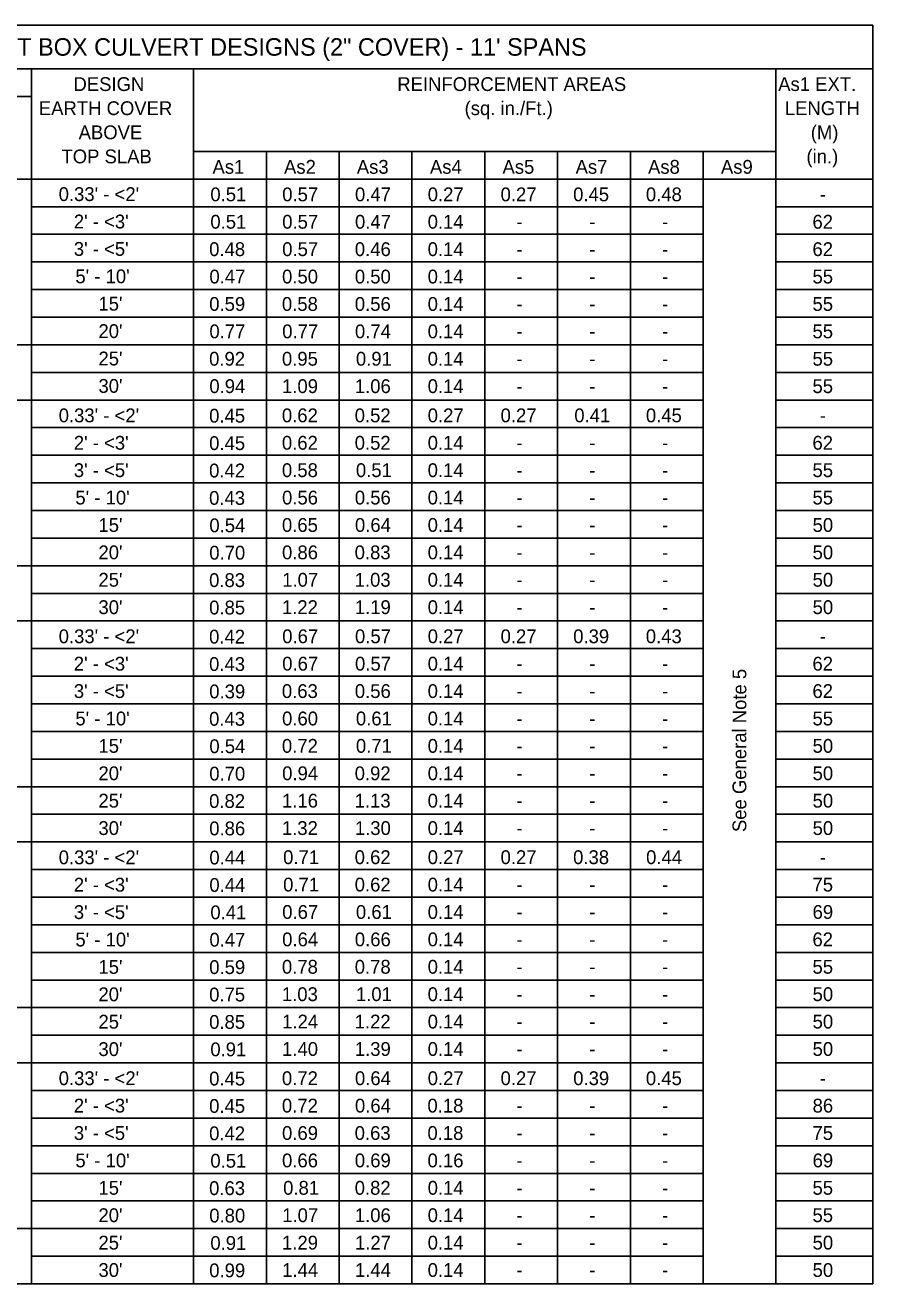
# Model space of a CAD drawing. Extents: x 10351.18 to 10353.4, y 76399.49 to 76400.59.
# Drawn here: x 10351.4 to 10351.787, y 76399.925 to 76400.5 of the extents above; entities that cross this region are included whole.
import ezdxf

# ---------------------------------------------------------------- set-up
doc = ezdxf.new("R2010")
doc.units = 0
doc.layers.add('AdhocPoint_dp', color=7, linetype='Continuous')
doc.layers.add('PlotBorder_dp', color=7, linetype='Continuous')

msp = doc.modelspace()

# ---------------------------------------------------------------- linework, layer by layer
at = {"layer": 'PlotBorder_dp'}
for p, q in [((10351.19191, 76400.49971), (10351.78665, 76400.49971)), ((10351.78665, 76400.49971), (10351.78665, 76399.92549)), ((10351.19191, 76400.47984), (10351.78665, 76400.47984)), ((10351.40299, 76400.47984), (10351.40299, 76399.92549)), ((10351.47687, 76400.47984), (10351.47687, 76399.92549)), ((10351.74246, 76400.47984), (10351.74246, 76399.92549)), ((10351.26055, 76400.46724), (10351.40299, 76400.46724)), ((10351.47687, 76400.44209), (10351.74246, 76400.44209)), ((10351.51007, 76400.44209), (10351.51007, 76399.92549)), ((10351.54327, 76400.44209), (10351.54327, 76399.92549)), ((10351.57647, 76400.44209), (10351.57647, 76399.92549)), ((10351.60967, 76400.44209), (10351.60967, 76399.92549)), ((10351.64287, 76400.44209), (10351.64287, 76399.92549)), ((10351.64287, 76400.44209), (10351.64287, 76399.92549)), ((10351.67606, 76400.44209), (10351.67606, 76399.92549)), ((10351.70926, 76400.44209), (10351.70926, 76399.92549)), ((10351.19191, 76400.42949), (10351.78665, 76400.42949)), ((10351.40299, 76400.41689), (10351.70926, 76400.41689)), ((10351.74246, 76400.41689), (10351.78665, 76400.41689)), ((10351.40299, 76400.40429), (10351.70926, 76400.40429)), ((10351.74246, 76400.40429), (10351.78665, 76400.40429)), ((10351.40299, 76400.39169), (10351.70926, 76400.39169)), ((10351.74246, 76400.39169), (10351.78665, 76400.39169)), ((10351.40299, 76400.37909), (10351.70926, 76400.37909)), ((10351.74246, 76400.37909), (10351.78665, 76400.37909)), ((10351.40299, 76400.36649), (10351.70926, 76400.36649)), ((10351.74246, 76400.36649), (10351.78665, 76400.36649)), ((10351.40299, 76400.35389), (10351.26055, 76400.35389)), ((10351.40299, 76400.35389), (10351.70926, 76400.35389)), ((10351.74246, 76400.35389), (10351.78665, 76400.35389)), ((10351.40299, 76400.34129), (10351.70926, 76400.34129)), ((10351.74246, 76400.34129), (10351.78665, 76400.34129)), ((10351.19191, 76400.32869), (10351.70926, 76400.32869)), ((10351.74246, 76400.32869), (10351.78665, 76400.32869)), ((10351.40299, 76400.31609), (10351.70926, 76400.31609)), ((10351.74246, 76400.31609), (10351.78665, 76400.31609)), ((10351.40299, 76400.30349), (10351.70926, 76400.30349)), ((10351.74246, 76400.30349), (10351.78665, 76400.30349)), ((10351.40299, 76400.29089), (10351.70926, 76400.29089)), ((10351.74246, 76400.29089), (10351.78665, 76400.29089)), ((10351.40299, 76400.27829), (10351.70926, 76400.27829)), ((10351.74246, 76400.27829), (10351.78665, 76400.27829)), ((10351.40299, 76400.26569), (10351.70926, 76400.26569)), ((10351.74246, 76400.26569), (10351.78665, 76400.26569)), ((10351.40299, 76400.25309), (10351.26055, 76400.25309)), ((10351.40299, 76400.25309), (10351.70926, 76400.25309)), ((10351.74246, 76400.25309), (10351.78665, 76400.25309)), ((10351.40299, 76400.24049), (10351.70926, 76400.24049)), ((10351.74246, 76400.24049), (10351.78665, 76400.24049)), ((10351.19191, 76400.22789), (10351.70926, 76400.22789)), ((10351.40362, 76400.22789), (10351.4758, 76400.22789)), ((10351.74246, 76400.22789), (10351.78665, 76400.22789)), ((10351.40299, 76400.21529), (10351.70926, 76400.21529)), ((10351.74246, 76400.21529), (10351.78665, 76400.21529)), ((10351.40299, 76400.20269), (10351.70926, 76400.20269)), ((10351.74246, 76400.20269), (10351.78665, 76400.20269)), ((10351.40299, 76400.19009), (10351.70926, 76400.19009)), ((10351.74246, 76400.19009), (10351.78665, 76400.19009)), ((10351.40299, 76400.17749), (10351.70926, 76400.17749)), ((10351.74246, 76400.17749), (10351.78665, 76400.17749)), ((10351.40299, 76400.16489), (10351.70926, 76400.16489)), ((10351.74246, 76400.16489), (10351.78665, 76400.16489)), ((10351.40299, 76400.15229), (10351.26055, 76400.15229)), ((10351.40299, 76400.15229), (10351.70926, 76400.15229)), ((10351.74246, 76400.15229), (10351.78665, 76400.15229)), ((10351.40299, 76400.13969), (10351.70926, 76400.13969)), ((10351.74246, 76400.13969), (10351.78665, 76400.13969)), ((10351.19191, 76400.12709), (10351.70926, 76400.12709)), ((10351.40362, 76400.12709), (10351.4758, 76400.12709)), ((10351.40362, 76400.12709), (10351.4758, 76400.12709)), ((10351.74246, 76400.12709), (10351.78665, 76400.12709)), ((10351.40299, 76400.11449), (10351.70926, 76400.11449)), ((10351.74246, 76400.11449), (10351.78665, 76400.11449)), ((10351.40299, 76400.10189), (10351.70926, 76400.10189)), ((10351.74246, 76400.10189), (10351.78665, 76400.10189)), ((10351.40299, 76400.08929), (10351.70926, 76400.08929)), ((10351.74246, 76400.08929), (10351.78665, 76400.08929)), ((10351.40299, 76400.07669), (10351.70926, 76400.07669)), ((10351.74246, 76400.07669), (10351.78665, 76400.07669)), ((10351.40299, 76400.06409), (10351.70926, 76400.06409)), ((10351.74246, 76400.06409), (10351.78665, 76400.06409)), ((10351.40299, 76400.05149), (10351.26055, 76400.05149)), ((10351.40299, 76400.05149), (10351.70926, 76400.05149)), ((10351.74246, 76400.05149), (10351.78665, 76400.05149)), ((10351.40299, 76400.03889), (10351.70926, 76400.03889)), ((10351.74246, 76400.03889), (10351.78665, 76400.03889)), ((10351.19191, 76400.02629), (10351.70926, 76400.02629)), ((10351.40362, 76400.02629), (10351.4758, 76400.02629)), ((10351.40362, 76400.02629), (10351.4758, 76400.02629)), ((10351.40362, 76400.02629), (10351.4758, 76400.02629)), ((10351.74246, 76400.02629), (10351.78665, 76400.02629)), ((10351.40299, 76400.01369), (10351.70926, 76400.01369)), ((10351.74246, 76400.01369), (10351.78665, 76400.01369)), ((10351.40299, 76400.00109), (10351.70926, 76400.00109)), ((10351.74246, 76400.00109), (10351.78665, 76400.00109)), ((10351.40299, 76399.98849), (10351.70926, 76399.98849)), ((10351.74246, 76399.98849), (10351.78665, 76399.98849)), ((10351.40299, 76399.97589), (10351.70926, 76399.97589)), ((10351.74246, 76399.97589), (10351.78665, 76399.97589)), ((10351.40299, 76399.96329), (10351.70926, 76399.96329)), ((10351.74246, 76399.96329), (10351.78665, 76399.96329)), ((10351.40299, 76399.95069), (10351.26055, 76399.95069)), ((10351.40299, 76399.95069), (10351.70926, 76399.95069)), ((10351.74246, 76399.95069), (10351.78665, 76399.95069)), ((10351.40299, 76399.93809), (10351.70926, 76399.93809)), ((10351.74246, 76399.93809), (10351.78665, 76399.93809)), ((10351.19191, 76399.92549), (10351.78665, 76399.92549))]:
    msp.add_line(p, q, dxfattribs=at)

# ---------------------------------------------------------------- texts
at = {"layer": 'AdhocPoint_dp'}
for s, height, p in [('TABLE 7 - STANDARD PRECAST BOX CULVERT DESIGNS (2" COVER) - 11\' SPANS', 0.008, (10351.23831, 76400.48578)), ('As1', 0.0063, (10351.48549, 76400.43192)), ('As2', 0.0063, (10351.51812, 76400.43192)), ('As3', 0.0063, (10351.55132, 76400.43192)), ('As4', 0.0063, (10351.58465, 76400.43192)), ('As5', 0.0063, (10351.61775, 76400.43192)), ('As7', 0.0063, (10351.65109, 76400.43192)), ('As8', 0.0063, (10351.68413, 76400.43192)), ('As9', 0.0063, (10351.71738, 76400.43192))]:
    msp.add_text(s, height=height, dxfattribs=at).set_placement(p)
msp.add_text('See General Note 5', height=0.0063, rotation=90, dxfattribs=at).set_placement((10351.72896, 76400.13159))
at = {"layer": 'PlotBorder_dp'}
for s, p in [('DESIGN', (10351.42209, 76400.46968)), ('REINFORCEMENT AREAS', (10351.56977, 76400.46968)), ('(sq. in./Ft.)', (10351.60047, 76400.45868)), ('EARTH COVER', (10351.4063, 76400.45868)), ('ABOVE', (10351.42444, 76400.44768)), ('TOP SLAB', (10351.41661, 76400.43668)), ("0.33' - <2'", (10351.41535, 76400.41948)), ('0.51', (10351.48452, 76400.41937)), ('0.57', (10351.51729, 76400.41937)), ('0.47', (10351.55049, 76400.41937)), ('0.27', (10351.58365, 76400.41937)), ('0.27', (10351.61688, 76400.41937)), ('0.45', (10351.64997, 76400.41937)), ('0.48', (10351.68315, 76400.41937)), ("2' - <3'", (10351.42225, 76400.40698)), ('0.51', (10351.48452, 76400.40687)), ('0.57', (10351.51729, 76400.40687)), ('0.47', (10351.55049, 76400.40687)), ('0.14', (10351.58363, 76400.40687)), ('-', (10351.62414, 76400.40687)), ('-', (10351.65735, 76400.40687)), ('-', (10351.69053, 76400.40687)), ("3' - <5'", (10351.42225, 76400.39448)), ('0.48', (10351.48397, 76400.39437)), ('0.57', (10351.51729, 76400.39437)), ('0.46', (10351.55041, 76400.39437)), ('0.14', (10351.58363, 76400.39437)), ('-', (10351.62414, 76400.39437)), ('-', (10351.65735, 76400.39437)), ('-', (10351.69053, 76400.39437)), ("5' - 10'", (10351.42296, 76400.38198)), ('0.47', (10351.48409, 76400.38187)), ('0.50', (10351.51722, 76400.38187)), ('0.50', (10351.55043, 76400.38187)), ('0.14', (10351.58363, 76400.38187)), ('-', (10351.62414, 76400.38187)), ('-', (10351.65735, 76400.38187)), ('-', (10351.69053, 76400.38187)), ("15'", (10351.43348, 76400.36948)), ('0.59', (10351.48401, 76400.36937)), ('0.58', (10351.51716, 76400.36937)), ('0.56', (10351.55041, 76400.36937)), ('0.14', (10351.58363, 76400.36937)), ('-', (10351.62414, 76400.36937)), ('-', (10351.65735, 76400.36937)), ('-', (10351.69053, 76400.36937)), ("20'", (10351.43348, 76400.35698)), ('0.77', (10351.48409, 76400.35687)), ('0.77', (10351.51729, 76400.35687)), ('0.74', (10351.55047, 76400.35687)), ('0.14', (10351.58363, 76400.35687)), ('-', (10351.62414, 76400.35687)), ('-', (10351.65735, 76400.35687)), ('-', (10351.69053, 76400.35687)), ("25'", (10351.43348, 76400.34448)), ('0.92', (10351.48395, 76400.34437)), ('0.95', (10351.51717, 76400.34437)), ('0.91', (10351.55091, 76400.34437)), ('0.14', (10351.58363, 76400.34437)), ('-', (10351.62414, 76400.34437)), ('-', (10351.65735, 76400.34437)), ('-', (10351.69053, 76400.34437)), ("30'", (10351.43348, 76400.33198)), ('0.94', (10351.48407, 76400.33187)), ('1.09', (10351.51721, 76400.33187)), ('1.06', (10351.55041, 76400.33187)), ('0.14', (10351.58363, 76400.33187)), ('-', (10351.62414, 76400.33187)), ('-', (10351.65735, 76400.33187)), ('-', (10351.69053, 76400.33187)), ("0.33' - <2'", (10351.41535, 76400.31854)), ('0.45', (10351.48397, 76400.31838)), ('0.62', (10351.51715, 76400.31854)), ('0.52', (10351.55035, 76400.31854)), ('0.27', (10351.58365, 76400.31854)), ('0.27', (10351.61688, 76400.31854)), ('0.41', (10351.65051, 76400.31854)), ('0.45', (10351.68315, 76400.31854)), ('-', (10351.76245, 76400.31854)), ("2' - <3'", (10351.42225, 76400.30604)), ('0.45', (10351.48397, 76400.30588)), ('0.62', (10351.51715, 76400.30604)), ('0.52', (10351.55035, 76400.30604)), ('0.14', (10351.58363, 76400.30604)), ('62', (10351.75912, 76400.30604)), ('-', (10351.62414, 76400.30604)), ('-', (10351.65735, 76400.30604)), ('-', (10351.69053, 76400.30604)), ("3' - <5'", (10351.42225, 76400.29354)), ('0.42', (10351.48395, 76400.29338)), ('0.58', (10351.51716, 76400.29354)), ('0.51', (10351.55091, 76400.29354)), ('0.14', (10351.58363, 76400.29354)), ('55', (10351.75914, 76400.29354)), ('-', (10351.62414, 76400.29354)), ('-', (10351.65735, 76400.29354)), ('-', (10351.69053, 76400.29354)), ("5' - 10'", (10351.42296, 76400.28104)), ('0.43', (10351.48394, 76400.28088)), ('0.56', (10351.51721, 76400.28104)), ('0.56', (10351.55041, 76400.28104)), ('0.14', (10351.58363, 76400.28104)), ('55', (10351.75914, 76400.28104)), ('-', (10351.62414, 76400.28104)), ('-', (10351.65735, 76400.28104)), ('-', (10351.69053, 76400.28104)), ("15'", (10351.43348, 76400.26854)), ('0.54', (10351.48407, 76400.26838)), ('0.65', (10351.51717, 76400.26854)), ('0.64', (10351.55047, 76400.26854)), ('0.14', (10351.58363, 76400.26854)), ('-', (10351.62414, 76400.26854)), ('-', (10351.65735, 76400.26854)), ('-', (10351.69053, 76400.26854)), ('50', (10351.75919, 76400.26854)), ("20'", (10351.43348, 76400.25604)), ('0.70', (10351.48403, 76400.25588)), ('0.86', (10351.51721, 76400.25604)), ('0.83', (10351.55034, 76400.25604)), ('0.14', (10351.58363, 76400.25604)), ('-', (10351.62414, 76400.25604)), ('-', (10351.65735, 76400.25604)), ('-', (10351.69053, 76400.25604)), ('50', (10351.75919, 76400.25604)), ("25'", (10351.43348, 76400.24354)), ('0.83', (10351.48394, 76400.24338)), ('1.07', (10351.51729, 76400.24354)), ('1.03', (10351.55034, 76400.24354)), ('0.14', (10351.58363, 76400.24354)), ('50', (10351.75919, 76400.24354)), ('-', (10351.62414, 76400.24354)), ('-', (10351.65735, 76400.24354)), ('-', (10351.69053, 76400.24354)), ("30'", (10351.43348, 76400.23104)), ('0.85', (10351.48397, 76400.23088)), ('1.22', (10351.51715, 76400.23104)), ('1.19', (10351.55041, 76400.23104)), ('0.14', (10351.58363, 76400.23104)), ('50', (10351.75919, 76400.23104)), ('-', (10351.62414, 76400.23104)), ('-', (10351.65735, 76400.23104)), ('-', (10351.69053, 76400.23104)), ("0.33' - <2'", (10351.41535, 76400.21776)), ('0.67', (10351.51729, 76400.21776)), ('0.57', (10351.55049, 76400.21776)), ('0.27', (10351.58365, 76400.21776)), ('0.27', (10351.61688, 76400.21776)), ('0.39', (10351.65001, 76400.21776)), ('0.43', (10351.68312, 76400.21776)), ('0.42', (10351.48395, 76400.2176)), ('-', (10351.76245, 76400.21776)), ("2' - <3'", (10351.42225, 76400.20526)), ('0.43', (10351.48394, 76400.2051)), ('0.67', (10351.51729, 76400.20526)), ('0.57', (10351.55049, 76400.20526)), ('0.14', (10351.58363, 76400.20526)), ('-', (10351.62414, 76400.20526)), ('-', (10351.65735, 76400.20526)), ('-', (10351.69053, 76400.20526)), ('62', (10351.75912, 76400.20526)), ("3' - <5'", (10351.42225, 76400.19276)), ('0.39', (10351.48401, 76400.1926)), ('0.63', (10351.51714, 76400.19276)), ('0.56', (10351.55041, 76400.19276)), ('0.14', (10351.58363, 76400.19276)), ('-', (10351.62414, 76400.19276)), ('-', (10351.65735, 76400.19276)), ('-', (10351.69053, 76400.19276)), ('62', (10351.75912, 76400.19276)), ("5' - 10'", (10351.42296, 76400.18026)), ('0.43', (10351.48394, 76400.1801)), ('0.60', (10351.51722, 76400.18026)), ('0.61', (10351.55091, 76400.18026)), ('0.14', (10351.58363, 76400.18026)), ('55', (10351.75914, 76400.18026)), ('-', (10351.62414, 76400.18026)), ('-', (10351.65735, 76400.18026)), ('-', (10351.69053, 76400.18026)), ("15'", (10351.43348, 76400.16776)), ('0.54', (10351.48407, 76400.1676)), ('0.72', (10351.51715, 76400.16776)), ('0.71', (10351.55091, 76400.16776)), ('0.14', (10351.58363, 76400.16776)), ('50', (10351.75919, 76400.16776)), ('-', (10351.62414, 76400.16776)), ('-', (10351.65735, 76400.16776)), ('-', (10351.69053, 76400.16776)), ("20'", (10351.43348, 76400.15526)), ('0.70', (10351.48403, 76400.1551)), ('0.94', (10351.51727, 76400.15526)), ('0.92', (10351.55035, 76400.15526)), ('0.14', (10351.58363, 76400.15526)), ('50', (10351.75919, 76400.15526)), ('-', (10351.62414, 76400.15526)), ('-', (10351.65735, 76400.15526)), ('-', (10351.69053, 76400.15526)), ("25'", (10351.43348, 76400.14276)), ('0.82', (10351.48395, 76400.1426)), ('1.16', (10351.51721, 76400.14276)), ('1.13', (10351.55034, 76400.14276)), ('0.14', (10351.58363, 76400.14276)), ('-', (10351.62414, 76400.14276)), ('-', (10351.65735, 76400.14276)), ('-', (10351.69053, 76400.14276)), ('50', (10351.75919, 76400.14276)), ("30'", (10351.43348, 76400.13026)), ('0.86', (10351.48401, 76400.1301)), ('1.32', (10351.51715, 76400.13026)), ('1.30', (10351.55043, 76400.13026)), ('0.14', (10351.58363, 76400.13026)), ('-', (10351.62414, 76400.13026)), ('-', (10351.65735, 76400.13026)), ('-', (10351.69053, 76400.13026)), ('50', (10351.75919, 76400.13026)), ("0.33' - <2'", (10351.41535, 76400.11692)), ('0.44', (10351.48407, 76400.11682)), ('0.71', (10351.51771, 76400.11698)), ('0.62', (10351.55035, 76400.11698)), ('0.27', (10351.58365, 76400.11698)), ('0.27', (10351.61688, 76400.11698)), ('0.38', (10351.64996, 76400.11698)), ('0.44', (10351.68325, 76400.11698)), ('-', (10351.76245, 76400.11698)), ("2' - <3'", (10351.42225, 76400.10442)), ('0.44', (10351.48407, 76400.10432)), ('0.71', (10351.51771, 76400.10448)), ('0.62', (10351.55035, 76400.10448)), ('0.14', (10351.58363, 76400.10448)), ('75', (10351.75914, 76400.10448)), ('-', (10351.62414, 76400.10448)), ('-', (10351.65735, 76400.10448)), ('-', (10351.69053, 76400.10448)), ("3' - <5'", (10351.42225, 76400.09192)), ('0.41', (10351.48452, 76400.09182)), ('0.67', (10351.51729, 76400.09198)), ('0.61', (10351.55091, 76400.09198)), ('0.14', (10351.58363, 76400.09198)), ('69', (10351.75918, 76400.09198)), ('-', (10351.62414, 76400.09198)), ('-', (10351.65735, 76400.09198)), ('-', (10351.69053, 76400.09198)), ("5' - 10'", (10351.42296, 76400.07942)), ('0.47', (10351.48409, 76400.07932)), ('0.64', (10351.51727, 76400.07948)), ('0.66', (10351.55041, 76400.07948)), ('0.14', (10351.58363, 76400.07948)), ('-', (10351.62414, 76400.07948)), ('-', (10351.65735, 76400.07948)), ('-', (10351.69053, 76400.07948)), ('62', (10351.75912, 76400.07948)), ("15'", (10351.43348, 76400.06692)), ('0.59', (10351.48401, 76400.06682)), ('0.78', (10351.51716, 76400.06698)), ('0.78', (10351.55037, 76400.06698)), ('0.14', (10351.58363, 76400.06698)), ('-', (10351.62414, 76400.06698)), ('-', (10351.65735, 76400.06698)), ('-', (10351.69053, 76400.06698)), ('55', (10351.75914, 76400.06698)), ("20'", (10351.43348, 76400.05442)), ('0.75', (10351.48397, 76400.05432)), ('1.03', (10351.51714, 76400.05448)), ('1.01', (10351.55091, 76400.05448)), ('0.14', (10351.58363, 76400.05448)), ('50', (10351.75919, 76400.05448)), ('-', (10351.62414, 76400.05448)), ('-', (10351.65735, 76400.05448)), ('-', (10351.69053, 76400.05448)), ("25'", (10351.43348, 76400.04192)), ('0.85', (10351.48397, 76400.04182)), ('1.24', (10351.51727, 76400.04198)), ('1.22', (10351.55035, 76400.04198)), ('0.14', (10351.58363, 76400.04198)), ('50', (10351.75919, 76400.04198)), ('-', (10351.62414, 76400.04198)), ('-', (10351.65735, 76400.04198)), ('-', (10351.69053, 76400.04198)), ("30'", (10351.43348, 76400.02942)), ('0.91', (10351.48452, 76400.02932)), ('1.40', (10351.51722, 76400.02948)), ('1.39', (10351.55041, 76400.02948)), ('0.14', (10351.58363, 76400.02948)), ('50', (10351.75919, 76400.02948)), ('-', (10351.62414, 76400.02948)), ('-', (10351.65735, 76400.02948)), ('-', (10351.69053, 76400.02948)), ("0.33' - <2'", (10351.41535, 76400.01614)), ('0.45', (10351.48397, 76400.01599)), ('0.72', (10351.51715, 76400.01614)), ('0.64', (10351.55047, 76400.01614)), ('0.27', (10351.58365, 76400.01614)), ('0.27', (10351.61688, 76400.01614)), ('0.39', (10351.65001, 76400.01614)), ('0.45', (10351.68315, 76400.01614)), ('-', (10351.76245, 76400.01614)), ("2' - <3'", (10351.42225, 76400.00364)), ('0.45', (10351.48397, 76400.00349)), ('0.72', (10351.51715, 76400.00364)), ('0.64', (10351.55047, 76400.00364)), ('0.18', (10351.58352, 76400.00364)), ('-', (10351.62414, 76400.00364)), ('-', (10351.65735, 76400.00364)), ('-', (10351.69053, 76400.00364)), ('86', (10351.75918, 76400.00364)), ("3' - <5'", (10351.42225, 76399.99114)), ('0.42', (10351.48395, 76399.99099)), ('0.69', (10351.51721, 76399.99114)), ('0.63', (10351.55034, 76399.99114)), ('0.18', (10351.58352, 76399.99114)), ('75', (10351.75914, 76399.99114)), ('-', (10351.62414, 76399.99114)), ('-', (10351.65735, 76399.99114)), ('-', (10351.69053, 76399.99114)), ("5' - 10'", (10351.42296, 76399.97864)), ('0.51', (10351.48452, 76399.97849)), ('0.66', (10351.51721, 76399.97864)), ('0.69', (10351.55041, 76399.97864)), ('0.16', (10351.58357, 76399.97864)), ('69', (10351.75918, 76399.97864)), ('-', (10351.62414, 76399.97864)), ('-', (10351.65735, 76399.97864)), ('-', (10351.69053, 76399.97864)), ("15'", (10351.43348, 76399.96614)), ('0.63', (10351.48394, 76399.96599)), ('0.81', (10351.51771, 76399.96614)), ('0.82', (10351.55035, 76399.96614)), ('0.14', (10351.58363, 76399.96614)), ('55', (10351.75914, 76399.96614)), ('-', (10351.62414, 76399.96614)), ('-', (10351.65735, 76399.96614)), ('-', (10351.69053, 76399.96614)), ("20'", (10351.43348, 76399.95364)), ('1.07', (10351.51729, 76399.95364)), ('1.06', (10351.55041, 76399.95364)), ('0.14', (10351.58363, 76399.95364)), ('0.80', (10351.48403, 76399.95349)), ('-', (10351.62414, 76399.95364)), ('-', (10351.65735, 76399.95364)), ('-', (10351.69053, 76399.95364)), ('55', (10351.75914, 76399.95364)), ("25'", (10351.43348, 76399.94114)), ('0.91', (10351.48452, 76399.94099)), ('1.29', (10351.51721, 76399.94114)), ('1.27', (10351.55049, 76399.94114)), ('0.14', (10351.58363, 76399.94114)), ('-', (10351.62414, 76399.94114)), ('-', (10351.65735, 76399.94114)), ('-', (10351.69053, 76399.94114)), ('50', (10351.75919, 76399.94114)), ("30'", (10351.43348, 76399.92864)), ('0.99', (10351.48401, 76399.92849)), ('1.44', (10351.51727, 76399.92864)), ('1.44', (10351.55047, 76399.92864)), ('0.14', (10351.58363, 76399.92864)), ('-', (10351.62414, 76399.92864)), ('-', (10351.65735, 76399.92864)), ('-', (10351.69053, 76399.92864)), ('50', (10351.75919, 76399.92864))]:
    msp.add_text(s, height=0.0063, dxfattribs=at).set_placement(p)
for s, p in [('As1 EXT.', (10351.74351, 76400.46968)), ('LENGTH', (10351.74653, 76400.45868)), ('(M)', (10351.75834, 76400.44768)), ('(in.)', (10351.75638, 76400.43668)), ('-', (10351.76245, 76400.41937)), ('62', (10351.75912, 76400.40687)), ('62', (10351.75912, 76400.39437)), ('55', (10351.75914, 76400.38187)), ('55', (10351.75914, 76400.36937)), ('55', (10351.75914, 76400.35687)), ('55', (10351.75914, 76400.34437)), ('55', (10351.75914, 76400.33187))]:
    msp.add_text(s, height=0.0063, rotation=360, dxfattribs=at).set_placement(p)

doc.saveas('drawing.dxf')
